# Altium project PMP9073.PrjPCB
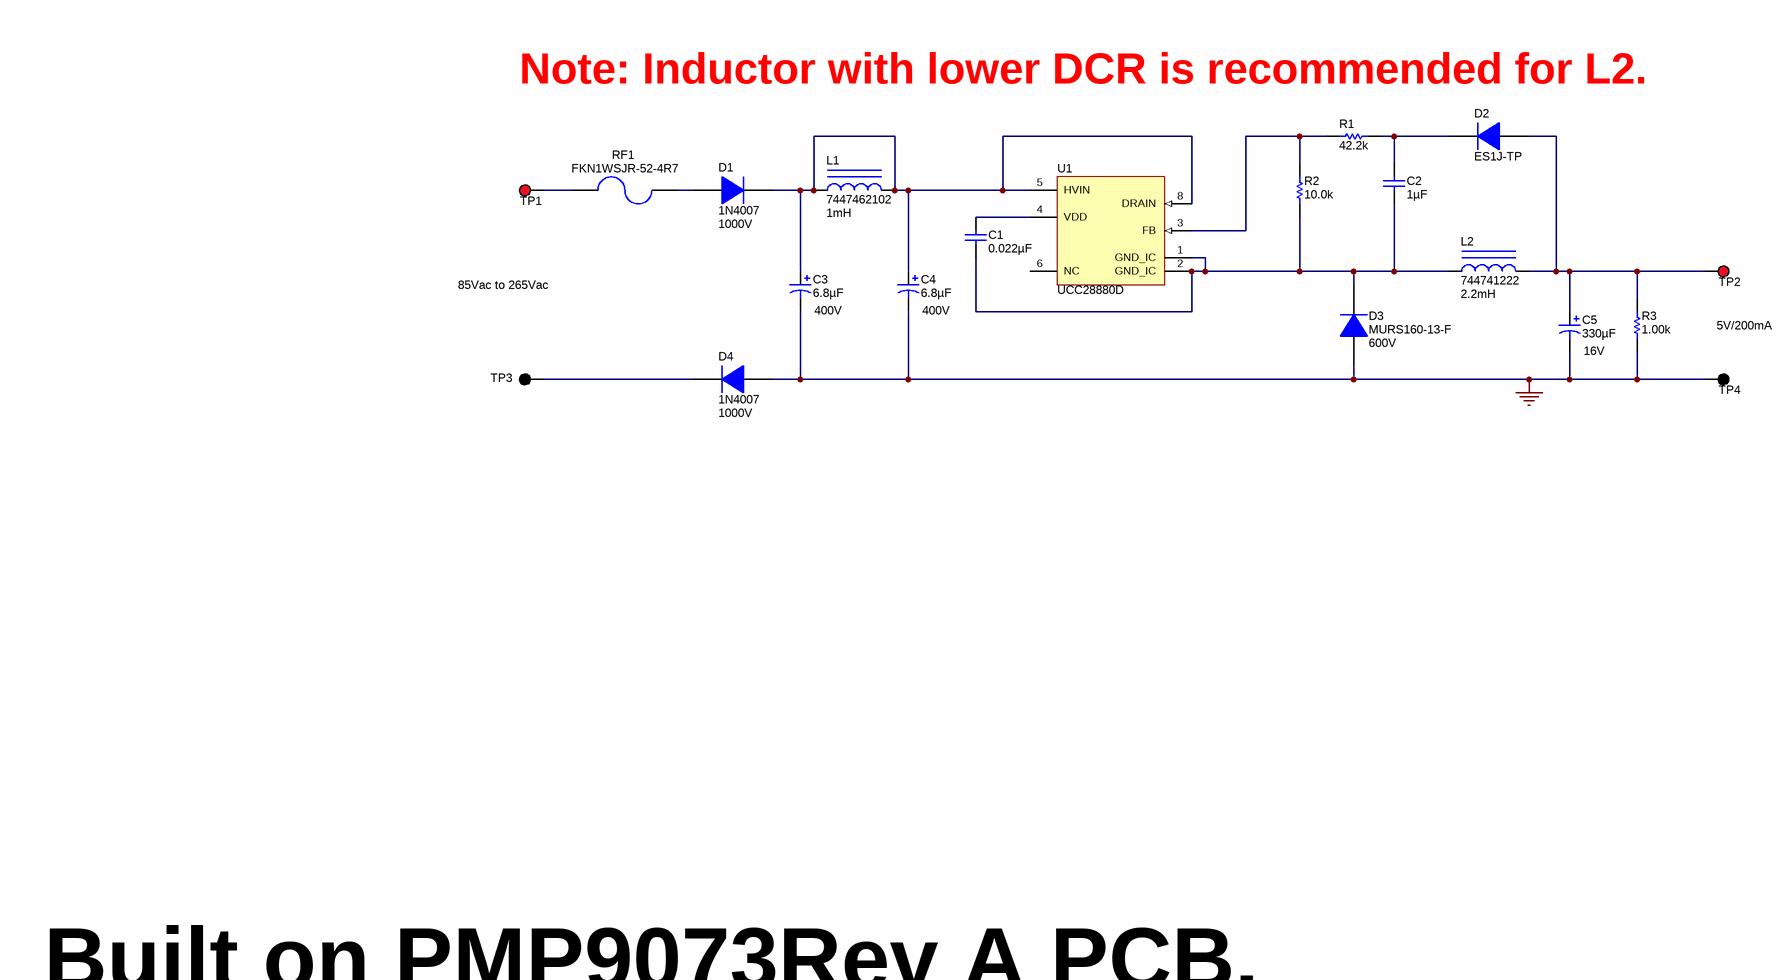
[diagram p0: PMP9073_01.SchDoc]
CopyrightYear: 2013; PCB_Layout: S Yu; PCB_Rev: A; PRJ_Customer: Public Release; PRJ_Engineer: Enter name of project lead; PRJ_Number: PMP9073; PRJ_Title: UCC28880 High-side Buck Converter; SCH_Rev: A; TechSupport: http://www.ti.com/support
2 sheets, 22 parts. Net scope: global (net labels, ports and power ports of the same name join across sheets).
Board file: PMP9073.PcbDoc
Sheets:
  PMP9073_01.SchDoc
  PMP9073_02.SchDoc

## Sheet PMP9073_01.SchDoc: 85Vac- 265Vac to 5V/0.2A
size 431 x 279 mm; Date: Not shown in title block; ApprovedBy: Not shown in title block; CheckedBy: Not shown in title block; Author: Not shown in title block; CompanyName: Not shown in title block; DrawnBy: S Yu; Engineer: Not shown in title block; Organization: Not shown in title block; Address1: Not shown in title block; Address2: Not shown in title block; Address3: Not shown in title block; Address4: Not shown in title block; DocumentNumber: 1; Revision: Use project parameter SCH_Rev; SheetNumber: 1; SheetTotal: 2; PageSetup: Record=PageOptions¦CenterHorizontal=True¦CenterVertical=True¦PrintScale=1.00¦XCorrection=1.00¦YCorrection=1.00¦PrintKind=0¦BorderSize=5000000¦LeftOffset=0¦BottomOffset=0¦Orientation=2¦PaperLength=1000¦PaperWidth=1000¦Scale=100¦PaperSource=15¦PrintQuality=600¦MediaType=1¦DitherType=10¦PaperKind=Letter¦PrintScaleMode=1

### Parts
C1  ValueDisplayed: 0.022µF  [1206]  (hidden comment: 12065C223KAT2A)
C2  ValueDisplayed: 1µF  [1206]  (hidden comment: CC1206KKX7R7BB105)
C3  ValueDisplayed: 6.8µF  Value2: 400V  [CAPPRD350W60D800H1100]  (hidden comment: 400AX6R8M8x11)
C4  ValueDisplayed: 6.8µF  Value2: 400V  [CAPPRD350W60D800H1100]  (hidden comment: 400AX6R8M8x11)
C5  ValueDisplayed: 330µF  Value2: 16V  [CAPPRD500W60D1000H1250]  (hidden comment: 16SEP330M)
D1  1N4007  value 1000V  [DO-41]
D2  ES1J-TP  [SMA]
D3  MURS160-13-F  value 600V  [SMB]
D4  1N4007  value 1000V  [DO-41]
L1  7447462102  ValueDisplayed: 1mH  [IND_WE-TI_XS]
L2  744741222  ValueDisplayed: 2.2mH  [IND_WE-TI_XS]
R1  ValueDisplayed: 42.2k  [0603]  (hidden comment: CRCW060342K2FKEA)
R2  value 10.0k  [0603]  (hidden comment: CRCW060310K0FKEA)
R3  ValueDisplayed: 1.00k  [1206]  (hidden comment: CRCW12061K00FKEA)
RF1  FKN1WSJR-52-4R7  [RESAD1524W55L900D150]
TP1  5000  [Keystone5000]  (value not drawn)
TP2  5000  [Keystone5000]  (value not drawn)
TP3  5001  [Keystone5001]  (value not drawn)
TP4  5001  [Keystone5001]  (value not drawn)
U1  UCC28880D  [D0007A_N]

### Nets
GND: C3.2(-) C4.2(-) C5.2(-) D3.2(A) D4.2(A) R3.1 TP4.1
NetC1_1: C1.1 U1.4(VDD)
NetC1_2: C1.2 C2.2 D3.1(K) L2.1 R2.1 U1.1(GND_IC) U1.2(GND_IC)
NetC2_1: C2.1 D2.1(K) R1.2
NetC3_1: C3.1(+) C4.1(+) D1.1(K) L1.1 L1.2 U1.5(HVIN) U1.8(DRAIN)
NetC5_1: C5.1(+) D2.2(A) L2.2 R3.2 TP2.1
NetD1_2: D1.2(A) RF1.1
NetD4_1: D4.1(K) TP3.1
NetR1_1: R1.1 R2.2 U1.3(FB)
NetRF1_2: RF1.2 TP1.1

Not connected (* = marked no-connect by the designer): U1 6(NC)

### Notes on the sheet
- Note: Inductor with lower DCR is recommended for L2.
- 85Vac to 265Vac
- 5V/200mA
- Built on PMP9073Rev A PCB.

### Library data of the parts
C1 = 12065C223KAT2A: CAP, CERM, 0.022uF, 50V, +/-10%, X7R, 1206; Manufacturer: AVX; Polarized: N; CompType: Capacitor; U/M: EA; Cap_F: 0.000000022; Tolerance_%: 10; ESR_Ohm: 0.079; Value1: 0.079 ohm; VDC_V: 50; TaMin_C: -55; TaMax_C: 125
C2 = CC1206KKX7R7BB105: CAP, CERM, 1 µF, 16 V, +/- 10%, X7R, 1206; Manufacturer: Yageo America; Polarized: N; CompType: Capacitor; Value: 1uF; U/M: EA; Cap_F: 0.000001; Tolerance_%: 10; Value1: Unknown; VDC_V: 16; Value2: 16V; TaMin_C: -55; TaMax_C: 125; SizeArea_mm2: 5.12; SizeAreaWB_mm2: 10.92; SizeX_mm: 3.2; SizeY_mm: 1.6; SizeZ_mm: 1.35; AEC Category: Q200
C3 C4 = 400AX6R8M8x11: CAP, AL, 6.8uF, 400V, +/-20%, TH; Manufacturer: Rubycon; Polarized: Y; CompType: Capacitor; U/M: EA; Cap_F: 0.0000068; Tolerance_%: 20; Value1: Unknown; VDC_V: 400; TaMin_C: -40; TaMax_C: 105; Cap_Case: 8x11
C5 = UVY2G4R7MPD: CAP ALUM POLY 330UF 20% 16V T/H; Manufacturer: Panasonic Electronic Components; Polarized: Y; CompType: Capacitor; U/M: EA; Cap_F: 0.0000047; Tolerance_%: 20; Value1: Unknown; VDC_V: 16; TaMin_C: -40; TaMax_C: 105; Cap_Case: 10x12.5
D1 D4 = 1N4007: Diode, P-N, 1000V, 1A, TH; Manufacturer: Fairchild Semiconductor; U/M: EA; Vf_V: 1.1; Value2: 1.1V; Io_A: 1; Vr_V: 1000; TJmax_C: 175; RJC_CperW: 50
D2 = ES1D-13-F: DIODE FAST REC 600V 1A DO214AC; Manufacturer: Diodes Inc.; U/M: EA; Io_A: 1; Vr_V: 600; TJmax_C: 150; RJC_CperW: 25; Type: Ultrafast
D3 = MURS160-13-F: Diode, Ultrafast, 600V, 1A, SMB; Manufacturer: Diodes Inc.; U/M: EA; Vf_V: 1.25; Value2: 1.25V; Io_A: 1; Vr_V: 600; TJmax_C: 150; RJC_CperW: 13
L1 = 7447462102: Inductor, Unshielded Drum Core, Ferrite, 1mH, 0.25A, 4.38 ohm, TH; Manufacturer: Wurth Elektronik eiSos; Ind_H: 1.0E-3; Imax_A: 0.25; Irms: 0.25A @ 40C rise; Isat: 0.27A @ 10% inductance drop; DCR_ohm: 4.38; U/M: EA
L2 = 7447462102: INDUCTOR 2200UH .21A RADIAL; Manufacturer: Wurth Elektronik eiSos; Value: 2.2mH; Ind_H: 2.2E-3; Material: Ferrite; U/M: EA
R1 = CRCW060342K2FKEA: RES, 42.2 k, 1%, 0.1 W, 0603; Manufacturer: Vishay-Dale; CompType: Resistor; Value: 42.2k; Res_ohm: 42200; Value_Code: 42k2; Tolerance_%: 1; Power_W: 0.1; Value2: 0.1W; VDC_V: 75; TempCo: 100 ppm/C; SizeArea_mm2: 1.28; SizeX_mm: 1.6; SizeY_mm: 0.8; EIA_Code: E96; U/M: EA; AEC Category: Q200
R2 = CRCW060310K0FKEA: RES, 10.0k ohm, 1%, 0.1W, 0603; Manufacturer: Vishay-Dale; CompType: Resistor; Res_ohm: 10000; Value_Code: 10k0; Tolerance_%: 1; Power_W: 0.1; VDC_V: 75; TempCo: 100 ppm/C; EIA_Code: E96; U/M: EA
R3 = CRCW12061K00FKEA: RES, 1.00 k, 1%, 0.25 W, 1206; Manufacturer: Vishay-Dale; CompType: Resistor; Value: 1.00k; Res_ohm: 1000; Value_Code: 1k00; Tolerance_%: 1; Power_W: 0.25; Value2: 0.25W; VDC_V: 200; TempCo: 100 ppm/C; SizeArea_mm2: 5.12; SizeX_mm: 3.2; SizeY_mm: 1.6; SizeZ_mm: 1.35; EIA_Code: E96; U/M: EA; AEC Category: Q200
RF1 = FKN1WSJR-52-4R7: RES, 4.7 ohm, 5%, 1W, Fusible, TH; Manufacturer: Yageo America; SymbolCreator: a0412235; CompType: Fusible Resistor; Res_ohm: 4.7; Value: 4.7; Value_Code: 4R70; Tolerance_%: 5; Power_W: 1; TempCo: 350 ppm/C; EIA_Code: E24; U/M: EA
TP1 TP2 = 5000: Test Point, Miniature, Red, TH; Manufacturer: Keystone; CompType: Test Point Loop; U/M: EA
TP3 TP4 = 5001: Test Point, TH, Miniature, Black; Manufacturer: Keystone; Alternate Manufacturer: Any; Alternate PartNumber: Equivalent; CompType: Test Point Loop; U/M: EA
U1 = UCC28880D: Low Quiescent Current Switcher IC for AC/DC Power Supplies, D0007A; Alternate Manufacturer: None; Manufacturer: Texas Instruments; SymbolCreator: a0411947; U/M: EA

## Sheet PMP9073_02.SchDoc
size 431 x 279 mm; Date: Not shown in title block; ApprovedBy: Not shown in title block; CheckedBy: Not shown in title block; Author: Not shown in title block; CompanyName: Not shown in title block; Engineer: Not shown in title block; Organization: Not shown in title block; Address1: Not shown in title block; Address2: Not shown in title block; Address3: Not shown in title block; Address4: Not shown in title block; DocumentNumber: 2; Revision: Use project parameter SCH_Rev; SheetNumber: 2; SheetTotal: 2; PageSetup: Record=PageOptions|CenterHorizontal=True|CenterVertical=True|PrintScale=1.00|XCorrection=1.00|YCorrection=1.00|PrintKind=0|BorderSize=5000000|LeftOffset=0|BottomOffset=0|Orientation=2|PaperLength=1000|PaperWidth=1000|Scale=100|PaperSource=15|PrintQuality=600|MediaType=1|DitherType=10|PaperKind=Letter|PrintScaleMode=1
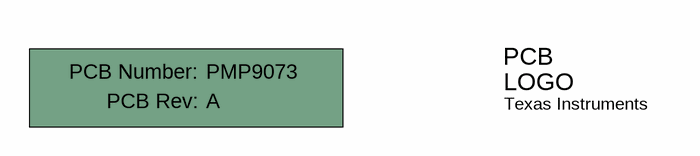
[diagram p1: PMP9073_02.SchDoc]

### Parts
!PCB1  Printed Circuit Board  (value not drawn)  (mechanical)
Logo1  Texas Instruments  [TI_Stacked_SolderMask_Small]  (no BOM)

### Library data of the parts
!PCB1 = PCB: Manufacturer: Any; PartNumber: PMP9073; SymbolCreator: a0412235
Logo1 = TI_Logo: Texas Instrument Corporate Signature; SymbolCreator: codlsc

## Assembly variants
001: all parts fitted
